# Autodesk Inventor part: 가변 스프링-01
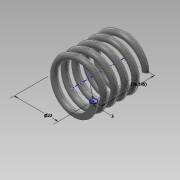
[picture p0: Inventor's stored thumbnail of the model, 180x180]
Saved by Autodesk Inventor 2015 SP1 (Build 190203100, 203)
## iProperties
Created: 2014-12
Part Number: 가변 스프링-01
Material: 강철, 탄소
Document SubType Name: Modeling
Designer: mypark
Density: 7.85 g/cm^3
Appearance: 반연마
Mass: 18.7215 g
Surface Area: 32.4279 cm^2
Volume: 2.3849 cm^3
Author: mypark
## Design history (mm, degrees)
sketch "스케치1"
  geometry: L1 (0, 0)-(11, 0); L2 (11, 0)-(11, 26.195); L3 (11, 26.195)-(0, 26.195); L4 (0, 26.195)-(0, 0); C1 r 1.5 at (11, 0)
  constraints: 8 end point, 2 parallel, 1 centre point, 1 coincident, 1 horizontal, 1 perpendicular
  dimensions: "d0" = 26.1955 distance of L1.end L2.end (derived); "d1" = 3 diameter of C1; "d2" = 22 diameter of C1.centre L4
feature "코일1" sketch "스케치1" pitch "d3" = 10; turns "d5" = 5; dims "d4" = 26.1955 (= d0), "d6" = 0, angle "d7" = 90 deg, angle "d8" = 90 deg, "d9" = 0, "d10" = 0
sketch "스케치2"
  geometry: L1 (-12.5, 0)-(-9.5, 0) reference; 1 further point
  constraints: 1 horizontal alignment
extrude "돌출1" cut sketch "스케치2" stored distance "d11" = 10; taper "d12" = 0 deg
node "작업 평면1"
sketch "스케치3"
  geometry: L1 (3, 0)-(0, 0) reference; 1 further point
  constraints: 1 horizontal alignment
extrude "돌출2" cut sketch "스케치3" stored distance "d13" = 10; taper "d14" = 0 deg
node "솔리드1"
node "절단 모서리 투영1"
node "절단 모서리 투영2"
